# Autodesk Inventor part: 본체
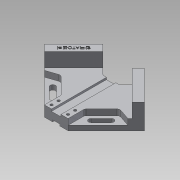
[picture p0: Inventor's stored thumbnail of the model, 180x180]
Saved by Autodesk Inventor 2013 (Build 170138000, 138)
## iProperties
Created: 2019-04
Part Number: 본체
Material: 알루미늄 6061
Document SubType Name: Modeling
Designer: Administrator
Density: 2.71 g/cm^3
Mass: 603.737 g
Surface Area: 426.536 cm^2
Volume: 222.781 cm^3
Author: Administrator
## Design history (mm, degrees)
sketch "스케치1"
  geometry: L1 (0, -84.853)-(0, 84.853); L2 (0, 84.853)-(-35.355, 49.497); L3 (-84.853, 0)-(-20, -64.853); L4 (0, 84.853)-(35.355, 49.497); L5 (84.853, 0)-(20, -64.853); L6 (-84.853, 0)-(84.853, 0); L7 (-35.355, 49.497)-(0, 14.142); L8 (35.355, 49.497)-(-7.497, 6.645); L9 (-35.355, 49.497)-(-84.853, 0); L10 (35.355, 49.497)-(84.853, 0); L11 (-14.005, 28.147)-(0, 28.147); L12 (-20, -64.853)-(0, -64.853); L13 (20, -64.853)-(0, -84.853); L14 (-20, -64.853)-(0, -84.853); L15 (0, -64.853)-(20, -64.853); L16 (-35.355, 49.497)-(-14.005, 28.147); L17 (0, 28.147)-(14.005, 28.147); L18 (0, 28.147)-(0, -64.853); 2 further points
  constraints: 36 end point, 7 point on line, 5 perpendicular, 4 horizontal, 4 parallel, 2 horizontal alignment, 2 midpoint, 2 vertical
  dimensions: "d0" = 120 distance of L1.end L3.start; "d2" = 50 distance between parallel lines of L4 L7; "d3" = 50 distance between parallel lines of L2 L8; "d5" = 20 distance from line of L12 L1.start; "d6" = 93 vertical distance of L17.end L12.end; "d7" = 93 distance of L12.end L11.end (derived)
extrude "돌출1" new body sketch "스케치1" distance "d8" = 18; taper "d9" = 0 deg
sketch "스케치2"
  geometry: L1 (-84.853, 0)-(-20, -64.853) reference; L2 (-20, -64.853)-(0, -64.853) reference; L3 (-35.355, 49.497)-(-84.853, 0) reference; L4 (-63.64, -21.213)-(-49.497, -7.071); L5 (-49.497, -7.071)-(-20, -36.569); L6 (-70.711, -14.142)-(-20, -64.853); L7 (-70.711, -14.142)-(-49.497, -7.071); L8 (-20, -64.853)-(-20, -36.569); 1 further point
  constraints: 10 end point, 3 point on line, 2 perpendicular, 1 parallel
  dimensions: "d10" = 30 distance from line of L4.end L3; "d11" = 20 distance between parallel lines of L5 L1; "d12" = 20 distance of L6.start L1.start; "d13" = 30 distance of L4.start L1.start (derived)
extrude "돌출7" cut sketch "스케치2" distance "d34" = 10; taper "d35" = 0 deg
sketch "스케치3"
  geometry: L1 (-14.005, 28.147)-(-35.355, 49.497) reference; L2 (-35.355, 49.497)-(-84.853, 0) reference; L3 (-84.853, 0)-(-70.711, -14.142) reference; L4 (-84.853, 0)-(-35.355, 49.497); L5 (-24.749, 38.891)-(-74.246, -10.607); 1 further point
  constraints: 4 end point, 2 perpendicular, 2 point on line
  dimensions: "d16" = 15 distance of L5.end L2.end
extrude "돌출8" join sketch "스케치3" distance "d36" = 24; taper "d37" = 0 deg
sketch "스케치5"
  geometry: L1 (-20, -64.853)-(0, -64.853) reference; L2 (0, -64.853)-(0, 28.147) reference; L3 (0, 28.147)-(-14.005, 28.147) reference; L4 (-8, -64.853)-(-8, 28.147); L5 (-8, 28.147)-(0, 28.147); L6 (0, -64.853)-(-8, -64.853); 1 further point
  constraints: 6 end point, 2 horizontal, 2 point on line, 1 vertical
  dimensions: "d27" = 8 distance from line of L2 L4.start
extrude "돌출5" cut sketch "스케치5" distance "d28" = 3.5; taper "d29" = 0 deg
sketch "스케치6"
  geometry: L1 (20, -64.853)-(0, -64.853) reference; L2 (0, 28.147)-(6, 28.147); L3 (6, 28.147)-(6, -64.853); L4 (6, -64.853)-(0, -64.853); L5 (0, -64.853)-(0, 28.147); 1 further point
  constraints: 8 end point, 2 parallel, 1 horizontal, 1 perpendicular, 1 point on line
  dimensions: "d30" = 6 distance between parallel lines of L5 L3
extrude "돌출6" cut sketch "스케치6" distance "d32" = 3; taper "d33" = 0 deg
sketch "스케치8"
  geometry: L1 (-20, -64.853)-(-70.711, -14.142) reference; L2 (-46.315, -18.031)-(-29.345, -35.002); L3 (-52.679, -24.395)-(-35.709, -41.366); L4 (-79.74, 9.029)-(-17.838, -52.872); L5 (-84.853, 0)-(-20, -64.853) reference; L6 (-35.355, 49.497)-(-84.853, 0) reference; A1 r 4.5 centre (-49.497, -21.213) between (-46.315, -18.031) and (-52.679, -24.395); A2 r 4.5 centre (-32.527, -38.184) between (-29.345, -35.002) and (-35.709, -41.366); 1 further point
  constraints: 6 end point, 4 point on circle, 4 tangent, 2 centre point, 2 parallel, 1 equal radius, 1 point on line
  dimensions: "d40" = 10 distance between parallel lines of L4 L5; "d41" = 9 diameter of A2; "d42" = 24 distance of A2.centre A1.centre; "d43" = 40 distance from line of A1.centre L6
extrude "돌출9" cut sketch "스케치8" stored distance "d44" = 24; taper "d45" = 0 deg
sketch "스케치10"
  geometry: L1 (20, -64.853)-(6, -64.853) reference; L2 (0, -64.853)-(0, 28.147) reference; 3 further points
  constraints: 1 vertical alignment
  dimensions: "d46" = 6 distance from line of point (14, -58.853) L1; "d47" = 12 distance of point (14, -58.853) point (14, -46.853); "d48" = 14 distance from line of point (14, -58.853) L2
hole "구멍1" sketch "스케치10" at (14, -58.853), (14, -46.853) diameter "d49" = 4.5; stored, may be unused: countersink angle "d53" = 90 deg, drill point angle "d55" = 118 deg; dims "d50" = 6, "d51" = 8, "d52" = 10, "d54" = 8
sketch "스케치11"
  geometry: L1 (-35.355, 49.497)-(-84.853, 0) reference; L2 (-24.749, 38.891)-(-35.355, 49.497) reference; 2 further points
  constraints: 1 other
  dimensions: "d56" = 7.5 distance from line of point (-54.801, 19.445) L1; "d57" = 35 distance from line of L2 point (-54.801, 19.445)
feature "엠보싱1" sketch "스케치11" dims "d58" = 0.5, "d59" = 0
fillet "모깎기1" dims "d60" = 5
node "솔리드1"
mirror "대칭1"
